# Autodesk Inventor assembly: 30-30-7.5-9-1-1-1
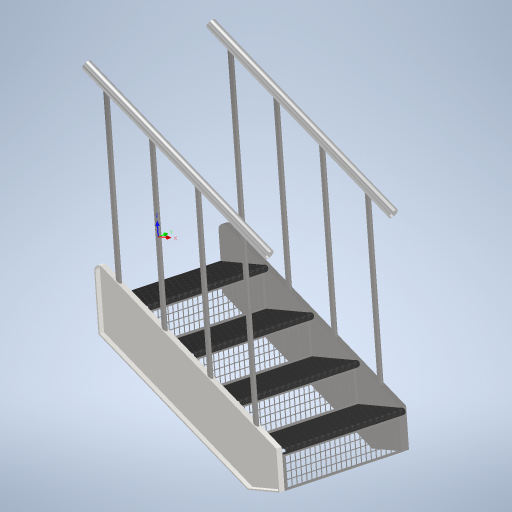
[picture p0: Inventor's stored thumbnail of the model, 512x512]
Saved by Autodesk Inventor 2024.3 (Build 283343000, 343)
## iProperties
Created: 2026-01
Part Number: 30-30-7.5-9-1-1-1
Description: Metal Stairs
Document SubType Name: Assembly
Designer: MichelleRasmussen
Company: Elevation Stair Company
RuleStatus: InUse
AfterAnyUserParamChange0: Type Name
Author: MichelleRasmussen
Run: 9.000 in
TheAngle: 39.81 deg
TargetRise: 7.250 in
Rise: 7.500 in
Height: 30.000 in
Width: 30.000 in
StringerWidth: 10.000 in
StringerThickness: 1.500 in
StringerLength: 46.861 in
NumberOfSteps: 5.000 ul
Length: 36.000 in
TreadThickness: 1.250 in
StringerStockLength: 48.000 in
RailingStockLength: 46.861 in
RailingWidth: 3.000 in
RailingThickness: 2.000 in
RightRail: True
LeftRail: True
StringerMaterial: Steel, Galvanized
TreadMaterial: Steel, Wrought
RiserMaterial: Steel, Galvanized
BalusterMaterial: Steel, Galvanized
HandrailMaterial: Aluminum 6061
HasHandrail: True
HasRiser: True
BalusterLength: 36.000 in
BalusterDia: 1.000 in
INDDataset: sample
Created: 2022-06
Designer: David Reaume
Author: David Reaume
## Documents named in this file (20)
- C:\Users\MichelleRasmussen\OneDrive\Documents\AutodeskTraining\Autodesk\Informed Design\Staircase Sample1\Staircase Sample\Staircase Sample.iam
- C:\Users\MichelleRasmussen\OneDrive\Documents\AutodeskTraining\Autodesk\Informed Design\Staircase Sample1\Staircase Sample\Stringer.ipt
- C:\Users\MichelleRasmussen\OneDrive\Documents\AutodeskTraining\Autodesk\Informed Design\Staircase Sample1\Staircase Sample\Tread.ipt
- C:\Users\MichelleRasmussen\OneDrive\Documents\AutodeskTraining\Autodesk\Informed Design\Staircase Sample1\Staircase Sample\Riser.ipt
- C:\Users\MichelleRasmussen\OneDrive\Documents\AutodeskTraining\Autodesk\Informed Design\Staircase Sample1\Staircase Sample\Baluster.ipt
- C:\Users\MichelleRasmussen\OneDrive\Documents\AutodeskTraining\Autodesk\Informed Design\Staircase Sample1\Staircase Sample\Railing.ipt
- C:\Users\MichelleRasmussen\OneDrive\Documents\AutodeskTraining\Autodesk\Informed Design\Staircase Sample1\Staircase Sample\Left Stringer_MIR.ipt
- C:\Users\partonj\Desktop\JP\Inventor Datasets\IND Samples (Analytics ID Added)\Inventor 2024\Staircase Sample1\Staircase Sample\Stringer.ipt
- C:\Users\partonj\Desktop\JP\Inventor Datasets\IND Samples (Analytics ID Added)\Inventor 2024\Staircase Sample1\Staircase Sample\Tread.ipt
- C:\Users\partonj\Desktop\JP\Inventor Datasets\IND Samples (Analytics ID Added)\Inventor 2024\Staircase Sample1\Staircase Sample\Riser.ipt
- C:\Users\partonj\Desktop\JP\Inventor Datasets\IND Samples (Analytics ID Added)\Inventor 2024\Staircase Sample1\Staircase Sample\Baluster.ipt
- C:\Users\partonj\Desktop\JP\Inventor Datasets\IND Samples (Analytics ID Added)\Inventor 2024\Staircase Sample1\Staircase Sample\Railing.ipt
- C:\Users\partonj\Desktop\JP\Inventor Datasets\IND Samples (Analytics ID Added)\Inventor 2024\Staircase Sample1\Staircase Sample\Left Stringer_MIR.ipt
- D:\MID Staircase\Stringer.ipt
- D:\MID Staircase\Tread.ipt
- D:\MID Staircase\Riser.ipt
- D:\MID Staircase\Baluster.ipt
- D:\MID Staircase\Railing.ipt
- D:\MID Staircase\Left Stringer_MIR.ipt
- C:\Users\MichelleRasmussen\OneDrive\Documents\AutodeskTraining\Autodesk\Informed Design\Staircase Sample1\Staircase Sample\Staircase Sample_Simplify_1.ipt
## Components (20 placed, 7 different names)
1. Stringer
2. Left Stringer_MIR:1
3. Right Railing
4. Left Railing — Flush:7, Flush:8, Flush:9
5. Tread:1
6. Tread:2
7. Tread:3
8. Tread:4
9. Riser:1
10. Riser:2
11. Riser:3
12. Riser:4
13. Baluster:1
14. Baluster:12
15. Baluster:15
16. Baluster:17
17. Baluster:7 — Flush:11, Flush:12
18. Baluster:8
19. Baluster:13
20. Baluster:16
## Component patterns: Tread Pattern (4 elements), Riser Pattern (4 elements), Right Baluster Pattern (4 elements), Left Baluster Pattern (4 elements)
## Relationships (5: Flush 5)
- Flush:7: Left Railing
- Flush:8: Left Railing
- Flush:9: Left Railing
- Flush:11: Baluster:7
- Flush:12: Baluster:7
## Named parameters: TheAngle = 6.94738 mm, StringerThickness = 38.1 mm, StringerLength = 1190.28205 mm, Length = 914.4 mm, TheAngleRounded = 6.94816 mm, StringerStockLength = 1219.2 mm, DiagonalTreadSpacing = 297.57051 mm, BalusterDia = 25.4 mm, BalusterLength = 914.4 mm, RailingStockLength = 1190.28205 mm, RailingWidth = 76.2 mm, RailingThickness = 50.8 mm, StringerSpacing = 876.3 mm
